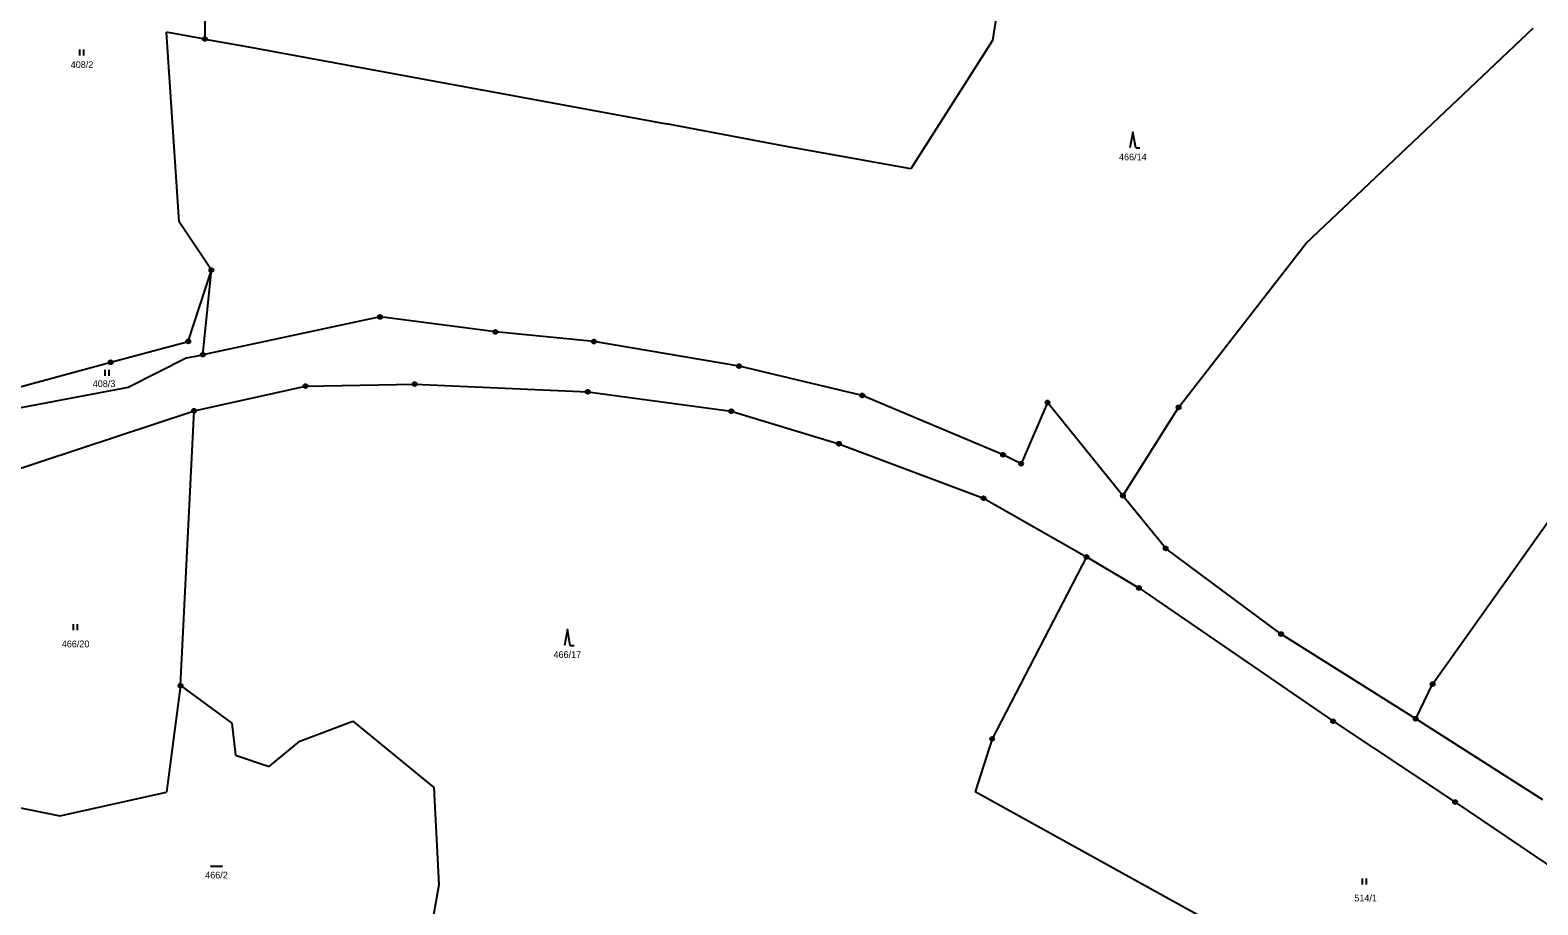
# Model space of a CAD drawing. Extents: x -739410 to -735662, y -942282 to -940043.
# Drawn here: x -736922.9 to -736544.3, y -941614.6 to -941395 of the extents above; entities that cross this region are included whole.
import ezdxf
from ezdxf.enums import TextEntityAlignment as Align

# ---------------------------------------------------------------- set-up
doc = ezdxf.new("R2010")
doc.units = 0
doc.header["$LTSCALE"] = 0.68
for name, color, linetype, lineweight in [('1', 7, 'Continuous', 25), ('3', 7, 'Continuous', 25), ('8', 7, 'Continuous', 25)]:
    doc.layers.add(name, color=color, linetype=linetype, lineweight=lineweight)
doc.layers.add('2', color=7, linetype='Continuous')

msp = doc.modelspace()

# ---------------------------------------------------------------- linework, layer by layer
at = {"layer": '1'}
for p, q in [((-736879.91, -941306.45), (-736879.07, -941397.22)), ((-736675.76, -941363.15), (-736681.22, -941397.57)), ((-736602.45, -941448.49), (-736545.43, -941394.51)), ((-736885.53, -941443.17), (-736888.71, -941395.49)), ((-736879.07, -941397.22), (-736888.71, -941395.49)), ((-736879.07, -941397.22), (-736869.01, -941399.04)), ((-736869.01, -941399.04), (-736763.1, -941418.55)), ((-736681.22, -941397.57), (-736701.76, -941429.8)), ((-736733.49, -941424.12), (-736763.1, -941418.55)), ((-736701.76, -941429.8), (-736733.49, -941424.12)), ((-736877.43, -941455.26), (-736885.53, -941443.17)), ((-736634.48, -941489.72), (-736602.45, -941448.49)), ((-736883.23, -941473.16), (-736877.43, -941455.26)), ((-736879.58, -941476.49), (-736877.43, -941455.26)), ((-736835.06, -941467.02), (-736879.58, -941476.49)), ((-736806.1, -941470.76), (-736835.06, -941467.02)), ((-736781.33, -941473.2), (-736806.1, -941470.76)), ((-736902.72, -941478.41), (-736883.23, -941473.16)), ((-736744.9, -941479.36), (-736781.33, -941473.2)), ((-736883.58, -941477.28), (-736898.32, -941484.72)), ((-736883.58, -941477.28), (-736879.58, -941476.49)), ((-736713.96, -941486.72), (-736744.9, -941479.36)), ((-736898.32, -941484.72), (-736931.16, -941490.89)), ((-736881.77, -941490.57), (-736853.78, -941484.38)), ((-736853.78, -941484.38), (-736826.35, -941483.89)), ((-736826.35, -941483.89), (-736782.91, -941485.82)), ((-736782.91, -941485.82), (-736746.83, -941490.69)), ((-736678.59, -941501.64), (-736713.96, -941486.72)), ((-736667.41, -941488.49), (-736674.05, -941503.88)), ((-736648.46, -941511.9), (-736667.41, -941488.49)), ((-736648.46, -941511.9), (-736634.48, -941489.72)), ((-736929.86, -941506.52), (-736881.77, -941490.57)), ((-736885.17, -941559.59), (-736881.77, -941490.57)), ((-736746.83, -941490.69), (-736719.79, -941498.84)), ((-736719.79, -941498.84), (-736683.48, -941512.54)), ((-736674.05, -941503.88), (-736678.59, -941501.64)), ((-736683.48, -941512.54), (-736657.62, -941527.27)), ((-736637.73, -941525.15), (-736648.46, -941511.9)), ((-736570.69, -941559.22), (-736537.92, -941513.11)), ((-736657.62, -941527.27), (-736681.32, -941572.97)), ((-736657.62, -941527.27), (-736644.46, -941535.07)), ((-736608.76, -941546.64), (-736637.73, -941525.15)), ((-736644.46, -941535.07), (-736595.68, -941568.54)), ((-736574.93, -941567.93), (-736608.76, -941546.64)), ((-736885.17, -941559.59), (-736888.66, -941586.34)), ((-736885.17, -941559.59), (-736872.28, -941568.99)), ((-736574.93, -941567.93), (-736570.69, -941559.22)), ((-736872.28, -941568.99), (-736871.4, -941577.07)), ((-736855.24, -941573.58), (-736841.91, -941568.55)), ((-736841.91, -941568.55), (-736821.59, -941585.16)), ((-736595.68, -941568.54), (-736565.04, -941588.83)), ((-736543.03, -941588.3), (-736574.93, -941567.93)), ((-736681.32, -941572.97), (-736685.55, -941586.27)), ((-736871.4, -941577.07), (-736862.88, -941579.92)), ((-736862.88, -941579.92), (-736855.24, -941573.58)), ((-736939.25, -941587.5), (-736915.52, -941592.28)), ((-736915.52, -941592.28), (-736888.66, -941586.34)), ((-736821.59, -941585.16), (-736820.28, -941609.6)), ((-736606.2, -941630.1), (-736685.55, -941586.27)), ((-736565.04, -941588.83), (-736517.32, -941621.13)), ((-736820.28, -941609.6), (-736822.24, -941620.53))]:
    msp.add_line(p, q, dxfattribs=at)
msp.add_lwpolyline([(-736931.16, -941490.89), (-736930.82, -941485.98), (-736902.72, -941478.41)], dxfattribs=at)
at = {"layer": '3'}
for p, q in [((-736910.431, -941401.39), (-736910.431, -941399.89)), ((-736909.43, -941401.39), (-736909.43, -941399.89)), ((-736645.24, -941424.58), (-736644.244, -941424.58)), ((-736904.101, -941481.78), (-736904.101, -941480.28)), ((-736903.1, -941481.78), (-736903.1, -941480.28)), ((-736912.041, -941545.64), (-736912.041, -941544.14)), ((-736911.04, -941545.64), (-736911.04, -941544.14)), ((-736787.27, -941549.52), (-736786.274, -941549.52)), ((-736877.638, -941604.9), (-736874.638, -941604.9)), ((-736588.271, -941609.57), (-736588.271, -941608.07)), ((-736587.27, -941609.57), (-736587.27, -941608.07))]:
    msp.add_line(p, q, dxfattribs=at)
for points in [[(-736645.24, -941424.58), (-736645.99, -941420.58), (-736646.74, -941424.58)], [(-736787.27, -941549.52), (-736788.02, -941545.52), (-736788.77, -941549.52)]]:
    msp.add_lwpolyline(points, dxfattribs=at)
at = {"layer": '8'}
for centre, radius in [((-736879.07, -941397.2199), 0.5), ((-736879.07, -941397.2199), 0.0303), ((-736877.43, -941455.2599), 0.5), ((-736877.43, -941455.2599), 0.0303), ((-736835.06, -941467.0199), 0.5), ((-736835.06, -941467.0199), 0.0303), ((-736806.1, -941470.7599), 0.5), ((-736806.1, -941470.7599), 0.0303), ((-736883.23, -941473.1599), 0.5), ((-736883.23, -941473.1599), 0.0303), ((-736781.33, -941473.1999), 0.5), ((-736781.33, -941473.1999), 0.0303), ((-736902.72, -941478.4099), 0.5), ((-736902.72, -941478.4099), 0.0303), ((-736879.58, -941476.4899), 0.5), ((-736879.58, -941476.4899), 0.0303), ((-736744.9, -941479.3599), 0.5), ((-736744.9, -941479.3599), 0.0303), ((-736853.78, -941484.3799), 0.5), ((-736853.78, -941484.3799), 0.0303), ((-736826.35, -941483.8899), 0.5), ((-736826.35, -941483.8899), 0.0303), ((-736782.91, -941485.8199), 0.5), ((-736782.91, -941485.8199), 0.0303), ((-736713.96, -941486.7199), 0.5), ((-736713.96, -941486.7199), 0.0303), ((-736667.41, -941488.4899), 0.5), ((-736667.41, -941488.4899), 0.0303), ((-736634.48, -941489.7199), 0.5), ((-736634.48, -941489.7199), 0.0303), ((-736881.77, -941490.5699), 0.5), ((-736881.77, -941490.5699), 0.0303), ((-736746.83, -941490.6899), 0.5), ((-736746.83, -941490.6899), 0.0303), ((-736719.79, -941498.8399), 0.5), ((-736719.79, -941498.8399), 0.0303), ((-736678.59, -941501.6399), 0.5), ((-736678.59, -941501.6399), 0.0303), ((-736674.05, -941503.8799), 0.5), ((-736674.05, -941503.8799), 0.0303), ((-736683.48, -941512.5399), 0.5), ((-736683.48, -941512.5399), 0.0303), ((-736648.46, -941511.8999), 0.5), ((-736648.46, -941511.8999), 0.0303), ((-736657.62, -941527.2699), 0.5), ((-736657.62, -941527.2699), 0.0303), ((-736637.73, -941525.1499), 0.5), ((-736637.73, -941525.1499), 0.0303), ((-736644.46, -941535.0699), 0.5), ((-736644.46, -941535.0699), 0.0303), ((-736608.76, -941546.6399), 0.5), ((-736608.76, -941546.6399), 0.0303), ((-736885.17, -941559.5899), 0.5), ((-736885.17, -941559.5899), 0.0303), ((-736570.69, -941559.2199), 0.5), ((-736570.69, -941559.2199), 0.0303), ((-736595.68, -941568.5399), 0.5), ((-736595.68, -941568.5399), 0.0303), ((-736574.93, -941567.9299), 0.5), ((-736574.93, -941567.9299), 0.0303), ((-736681.32, -941572.9699), 0.5), ((-736681.32, -941572.9699), 0.0303), ((-736565.04, -941588.8299), 0.5), ((-736565.04, -941588.8299), 0.0303)]:
    msp.add_circle(centre, radius, dxfattribs=at)

# ---------------------------------------------------------------- texts
at = {"layer": '2'}
for s, p in [('408/2', (-736909.92, -941404.515)), ('466/14', (-736645.99, -941427.705)), ('408/3', (-736904.39, -941484.635)), ('466/20', (-736911.53, -941549.975)), ('466/17', (-736788.02, -941552.645)), ('466/2', (-736876.14, -941608.025)), ('514/1', (-736587.52, -941613.785))]:
    msp.add_text(s, height=1.7, dxfattribs=at).set_placement(p, align=Align.CENTER)

doc.saveas('drawing.dxf')
